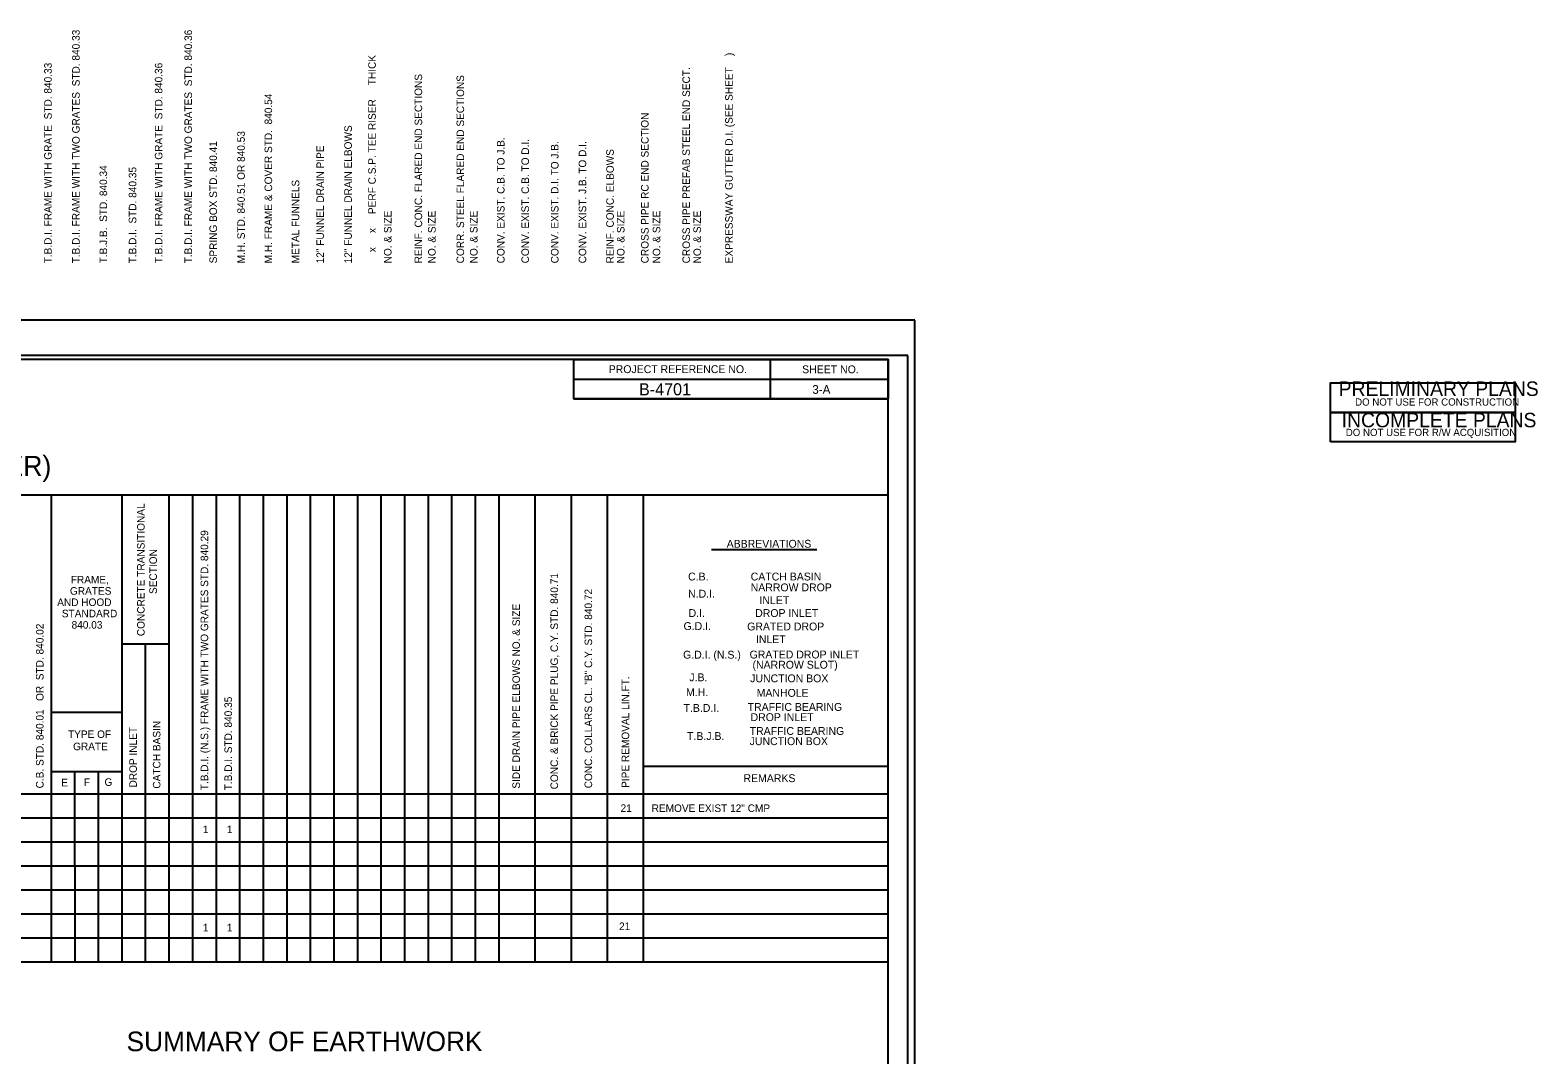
# Model space of a CAD drawing. Extents: x 573885.1 to 573944.9, y -53259.7 to -53181.6.
# Drawn here: x 573925.66 to 573944.85, y -53247.09 to -53234.04 of the extents above; entities that cross this region are included whole.
import ezdxf

# ---------------------------------------------------------------- set-up
doc = ezdxf.new("R2010")
doc.units = 0
for name, color, linetype in [('Prop DSN Text', 7, 'Continuous'), ('Sheet Cutting Line CELL', 7, 'Continuous'), ('Sheet Pipe Summary CELL', 7, 'Continuous'), ('Sheet Plot Border Inside CELL', 7, 'Continuous'), ('Sheet Plot Border Outside CELL', 7, 'Continuous'), ('Sheet Sticker Incomplete CELL', 7, 'Continuous'), ('Sheet Sticker Preliminary CELL', 7, 'Continuous'), ('Sheet Summary Combination CELL', 7, 'Continuous'), ('Sheet Summary Combination Grid CELL', 7, 'Continuous')]:
    doc.layers.add(name, color=color, linetype=linetype)

msp = doc.modelspace()

# ---------------------------------------------------------------- linework, layer by layer
at = {"layer": 'Sheet Cutting Line CELL'}
msp.add_line((573936.919, -53237.733), (573903.239, -53237.733), dxfattribs=at)
at = {"layer": 'Sheet Plot Border Inside CELL'}
msp.add_lwpolyline([(573936.829, -53238.182), (573903.499, -53238.182), (573903.499, -53259.284), (573936.829, -53259.284)], close=True, dxfattribs=at)
at = {"layer": 'Sheet Plot Border Outside CELL'}
msp.add_lwpolyline([(573936.919, -53237.733), (573903.239, -53237.733), (573903.239, -53259.733), (573936.919, -53259.733)], close=True, dxfattribs=at)
at = {"layer": 'Sheet Sticker Incomplete CELL'}
msp.add_lwpolyline([(573942.211, -53239.284), (573942.211, -53238.908), (573944.563, -53238.908), (573944.563, -53239.284)], close=True, dxfattribs=at)
at = {"layer": 'Sheet Sticker Preliminary CELL'}
msp.add_lwpolyline([(573942.211, -53238.908), (573942.211, -53238.532), (573944.563, -53238.532), (573944.563, -53238.908)], close=True, dxfattribs=at)
at = {"layer": 'Sheet Summary Combination CELL'}
for p, q in [((573935.079, -53238.234), (573935.079, -53238.734)), ((573932.578, -53238.484), (573936.579, -53238.484)), ((573932.578, -53238.734), (573936.579, -53238.734)), ((573935.673, -53240.658), (573934.333, -53240.658))]:
    msp.add_line(p, q, dxfattribs=at)
for points in [[(573936.579, -53238.233), (573906.579, -53238.233), (573906.579, -53259.233), (573936.579, -53259.233)], [(573932.578, -53238.233), (573936.579, -53238.233), (573936.579, -53238.734), (573932.578, -53238.734)]]:
    msp.add_lwpolyline(points, close=True, dxfattribs=at)
at = {"layer": 'Sheet Summary Combination Grid CELL'}
for p, q in [((573936.567, -53239.961), (573906.567, -53239.963)), ((573925.928, -53245.908), (573925.927, -53239.963)), ((573926.827, -53245.908), (573926.827, -53239.962)), ((573927.427, -53245.908), (573927.427, -53239.962)), ((573927.727, -53245.908), (573927.727, -53239.962)), ((573928.027, -53245.908), (573928.027, -53239.962)), ((573928.327, -53245.908), (573928.327, -53239.962)), ((573928.627, -53245.908), (573928.627, -53239.962)), ((573928.927, -53245.908), (573928.927, -53239.962)), ((573929.227, -53245.908), (573929.227, -53239.962)), ((573929.527, -53245.908), (573929.527, -53239.962)), ((573929.827, -53245.908), (573929.827, -53239.962)), ((573930.127, -53245.908), (573930.127, -53239.962)), ((573930.427, -53245.908), (573930.427, -53239.962)), ((573930.727, -53245.908), (573930.727, -53239.962)), ((573931.027, -53245.908), (573931.027, -53239.962)), ((573931.327, -53245.908), (573931.327, -53239.962)), ((573931.627, -53245.908), (573931.627, -53239.962)), ((573932.087, -53245.908), (573932.087, -53239.962)), ((573932.547, -53245.908), (573932.547, -53239.962)), ((573933.007, -53245.908), (573933.007, -53239.962)), ((573933.467, -53245.908), (573933.467, -53239.962)), ((573927.427, -53241.857), (573926.827, -53241.857)), ((573927.127, -53245.908), (573927.127, -53241.857)), ((573926.827, -53242.728), (573925.927, -53242.728)), ((573926.827, -53243.484), (573925.927, -53243.484)), ((573926.228, -53245.908), (573926.227, -53243.484)), ((573926.528, -53245.908), (573926.527, -53243.484)), ((573936.579, -53243.416), (573933.467, -53243.416)), ((573936.567, -53243.769), (573906.567, -53243.769)), ((573936.567, -53244.075), (573906.567, -53244.075)), ((573936.567, -53244.38), (573906.567, -53244.38)), ((573936.567, -53244.685), (573906.567, -53244.685)), ((573936.567, -53244.991), (573906.567, -53244.991)), ((573936.567, -53245.296), (573906.567, -53245.296)), ((573936.567, -53245.602), (573906.567, -53245.602)), ((573936.567, -53245.907), (573906.567, -53245.907))]:
    msp.add_line(p, q, dxfattribs=at)

# ---------------------------------------------------------------- texts
at = {"layer": 'Prop DSN Text'}
for s, height, p in [('B-4701', 0.1535, (573933.408, -53238.69)), ('3-A', 0.1109, (573935.614, -53238.671))]:
    msp.add_text(s, height=height, dxfattribs=at).set_placement(p)
at = {"layer": 'Sheet Pipe Summary CELL'}
for s, p in [('C.B.', (573934.033, -53241.047)), ('CATCH BASIN', (573934.83, -53241.047)), ('N.D.I.', (573934.033, -53241.266)), ('NARROW DROP', (573934.83, -53241.185)), ('   INLET', (573934.83, -53241.348)), ('G.D.I.', (573933.975, -53241.678)), ('D.I.', (573934.039, -53241.512)), ('GRATED DROP', (573934.785, -53241.683)), ('DROP INLET', (573934.887, -53241.512)), ('   INLET', (573934.785, -53241.845)), ('G.D.I. (N.S.)', (573933.969, -53242.042)), ('J.B.', (573934.049, -53242.33)), ('JUNCTION BOX', (573934.823, -53242.343)), ('M.H.', (573934.007, -53242.519)), ('MANHOLE', (573934.906, -53242.528)), ('T.B.D.I.', (573933.975, -53242.72)), ('TRAFFIC BEARING', (573934.791, -53242.707)), (' DROP INLET', (573934.791, -53242.837)), ('TRAFFIC BEARING', (573934.817, -53243.013)), ('T.B.J.B.', (573934.02, -53243.078)), ('JUNCTION BOX', (573934.817, -53243.143))]:
    msp.add_text(s, height=0.1, dxfattribs=at).set_placement(p)
for s, p in [('GRATED DROP INLET', (573934.816, -53242.04)), (' (NARROW SLOT)', (573934.816, -53242.17))]:
    msp.add_text(s, height=0.1, rotation=0.0274, dxfattribs=at).set_placement(p)
at = {"layer": 'Sheet Sticker Incomplete CELL'}
for s, height, p in [('INCOMPLETE PLANS', 0.18432, (573942.354, -53239.097)), ('DO NOT USE FOR R/W ACQUISITION', 0.09216, (573942.406, -53239.208))]:
    msp.add_text(s, height=height, dxfattribs=at).set_placement(p)
at = {"layer": 'Sheet Sticker Preliminary CELL'}
for s, height, p in [('PRELIMINARY PLANS', 0.18432, (573942.315, -53238.698)), ('DO NOT USE FOR CONSTRUCTION', 0.09216, (573942.525, -53238.821))]:
    msp.add_text(s, height=height, dxfattribs=at).set_placement(p)
at = {"layer": 'Sheet Summary Combination CELL'}
for s, height, rotation, p in [('T.B.D.I. FRAME WITH TWO GRATES  STD. 840.33', 0.096, 90, (573926.287, -53237.01)), ('T.B.D.I. FRAME WITH TWO GRATES  STD. 840.36', 0.096, 90, (573927.717, -53237.01)), ('T.B.D.I. FRAME WITH GRATE  STD. 840.33', 0.096, 90, (573925.931, -53237.01)), ('T.B.D.I. FRAME WITH GRATE  STD. 840.36', 0.096, 90, (573927.34, -53237.01)), ('    x     x     PERF C.S.P. TEE RISER     THICK', 0.096, 90, (573930.057, -53237.01)), ('EXPRESSWAY GUTTER D.I. (SEE SHEET    )', 0.096, 90, (573934.601, -53237.01)), ('REINF. CONC. FLARED END SECTIONS', 0.096, 90, (573930.647, -53237.01)), ('CORR. STEEL FLARED END SECTIONS', 0.096, 90, (573931.181, -53237.01)), ('CROSS PIPE PREFAB STEEL END SECT.', 0.096, 90, (573934.057, -53237.01)), ('M.H. FRAME & COVER STD.  840.54', 0.096, 90, (573928.737, -53237.01)), ('12" FUNNEL DRAIN ELBOWS', 0.096, 90, (573929.752, -53237.01)), ('CROSS PIPE RC END SECTION', 0.096, 90, (573933.53, -53237.01)), ('M.H. STD. 840.51 OR 840.53', 0.096, 90.0267, (573928.39, -53237.01)), ('CONV. EXIST. C.B. TO J.B.', 0.096, 90, (573931.696, -53237.01)), ('CONV. EXIST. C.B. TO D.I.', 0.096, 90, (573932.007, -53237.01)), ('SPRING BOX STD. 840.41', 0.096, 90, (573928.035, -53237.01)), ('12" FUNNEL DRAIN PIPE', 0.096, 90, (573929.397, -53237.01)), ('CONV. EXIST. D.I. TO J.B.', 0.096, 90, (573932.383, -53237.01)), ('CONV. EXIST. J.B. TO D.I.', 0.096, 90, (573932.736, -53237.01)), ('REINF. CONC. ELBOWS ', 0.096, 90, (573933.087, -53237.01)), ('T.B.J.B.  STD. 840.34', 0.096, 90, (573926.636, -53237.01)), ('T.B.D.I.  STD. 840.35', 0.096, 90, (573927.008, -53237.01)), ('METAL FUNNELS', 0.096, 90, (573929.083, -53237.01)), ('NO. & SIZE', 0.096, 90, (573930.257, -53237.01)), ('NO. & SIZE', 0.096, 90, (573930.819, -53237.01)), ('NO. & SIZE', 0.096, 90, (573931.352, -53237.01)), ('NO. & SIZE', 0.096, 90, (573933.223, -53237.01)), ('NO. & SIZE', 0.096, 90, (573933.679, -53237.01)), ('NO. & SIZE', 0.096, 90, (573934.197, -53237.01)), ('CONCRETE TRANSITIONAL', 0.096, 90, (573927.114, -53241.756)), ('T.B.D.I. (N.S.) FRAME WITH TWO GRATES STD. 840.29', 0.096, 90, (573927.923, -53243.717)), ('SECTION', 0.096, 90, (573927.27, -53241.219)), ('CONC. & BRICK PIPE PLUG, C.Y. STD. 840.71', 0.096, 90, (573932.377, -53243.706)), ('CONC. COLLARS CL. "B" C.Y. STD. 840.72', 0.096, 90, (573932.811, -53243.693)), ('SIDE DRAIN PIPE ELBOWS NO. & SIZE', 0.096, 90, (573931.892, -53243.698)), ('C.B. STD. 840.01   OR  STD. 840.02', 0.096, 90, (573925.827, -53243.694)), ('PIPE REMOVAL LIN.FT.', 0.096, 90, (573933.283, -53243.687)), ('T.B.D.I. STD. 840.35', 0.096, 90, (573928.226, -53243.718)), ('DROP INLET', 0.096, 90, (573927.015, -53243.682)), ('CATCH BASIN', 0.096, 90, (573927.315, -53243.697)), ('SUMMARY OF EARTHWORK', 0.25, 0.0119, (573926.884, -53247.04))]:
    msp.add_text(s, height=height, rotation=rotation, dxfattribs=at).set_placement(p)
for s, height, p in [('PROJECT REFERENCE NO.', 0.1, (573933.022, -53238.407)), ('SHEET NO.', 0.1, (573935.485, -53238.409)), ('LIST OF PIPES, ENDWALLS, ETC. (FOR PIPES 48" & UNDER)', 0.254, (573916.18, -53239.715)), ('ABBREVIATIONS', 0.1, (573934.524, -53240.63)), ('FRAME,', 0.096, (573926.174, -53241.084)), ('GRATES', 0.096, (573926.163, -53241.228)), ('AND HOOD', 0.096, (573926.001, -53241.372)), ('STANDARD', 0.096, (573926.06, -53241.516)), ('840.03', 0.096, (573926.184, -53241.66)), ('TYPE OF', 0.096, (573926.138, -53243.052)), ('GRATE', 0.096, (573926.203, -53243.208)), ('REMARKS', 0.1, (573934.738, -53243.614)), ('E', 0.096, (573926.052, -53243.668)), ('F', 0.096, (573926.34, -53243.662)), ('G', 0.096, (573926.603, -53243.662))]:
    msp.add_text(s, height=height, dxfattribs=at).set_placement(p)
at = {"layer": 'Sheet Summary Combination Grid CELL'}
for s, p in [('21', (573933.173, -53243.994)), ('REMOVE EXIST 12" CMP', (573933.569, -53243.994)), ('1', (573927.855, -53244.264)), ('1', (573928.16, -53244.264)), ('1', (573927.855, -53245.514)), ('1', (573928.16, -53245.514)), ('21', (573933.154, -53245.497))]:
    msp.add_text(s, height=0.096, dxfattribs=at).set_placement(p)

doc.saveas('drawing.dxf')
